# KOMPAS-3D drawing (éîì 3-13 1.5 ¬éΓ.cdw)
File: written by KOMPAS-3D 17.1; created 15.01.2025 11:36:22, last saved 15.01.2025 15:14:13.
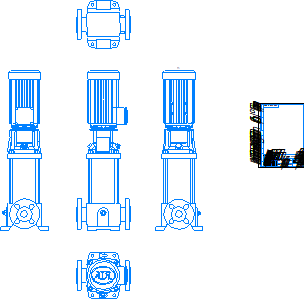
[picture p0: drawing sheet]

Sheet 1: A4, portrait

Title block, sheet 1: name: ВМН 3-13 1.1 кВт; designation: ВМН 3-13 1.1 кВт; material: Сталь 10  ГОСТ 1050-2013; mass: 68,16; sheets: 1; sheet format: A4; stored path: \\adlc.lan\data\АДЛ_ПКД\3D-модели\ADL production\Насосы ГРАНПАМП\Насосы ВМН\ВМН3\KOMPAS 3D\ВМН 3-13 1.5 кВт.cdw

Views: Проекционный вид 2, Проекционный вид 3, Проекционный вид 4, Проекционный вид 5
Referenced files in \\adlc.lan\data\АДЛ_ПКД\3D-модели\ADL production\Насосы ГРАНПАМП\Насосы ВМН\ВМН3\KOMPAS 3D\: ВМН 3-13 1.1 кВт.m3d
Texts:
  Andrey
  АДЛ
Dimensions and other numbers on the sheet: 1:1; 1; 68,16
